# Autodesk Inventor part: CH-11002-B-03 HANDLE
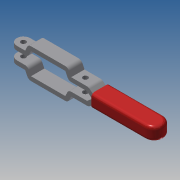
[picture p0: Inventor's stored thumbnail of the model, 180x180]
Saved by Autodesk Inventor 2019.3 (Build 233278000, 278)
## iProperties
Created: 2012-09
Part Number: CH-11002-B-03 HANDLE
Material: Ogólny
Document SubType Name: Modeling
Designer: CADENGINEERING4
Density: 1 g/cm^3
Appearance: Domyślna
Author: CADENGINEERING4
Revision Number: ÈÎºÎ
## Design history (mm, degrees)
feature "ÇÐ³ý-À­Éì1"
feature "¾µÏò1"
feature "Ô²½Ç2"
node "Bryła1"
node "Bryła2"
node "Bryła3"
